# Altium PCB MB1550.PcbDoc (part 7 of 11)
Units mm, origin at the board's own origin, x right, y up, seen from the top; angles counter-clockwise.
Board outline 154.81 x 170.69 mm, 6 copper layers (Top Layer, Signal Layer 1, Signal Layer 2, Signal Layer 3, Signal Layer 4, Bottom Layer), stack 1.49 mm thick; 810 components, 633 nets, 2973 pads, 2150 vias.
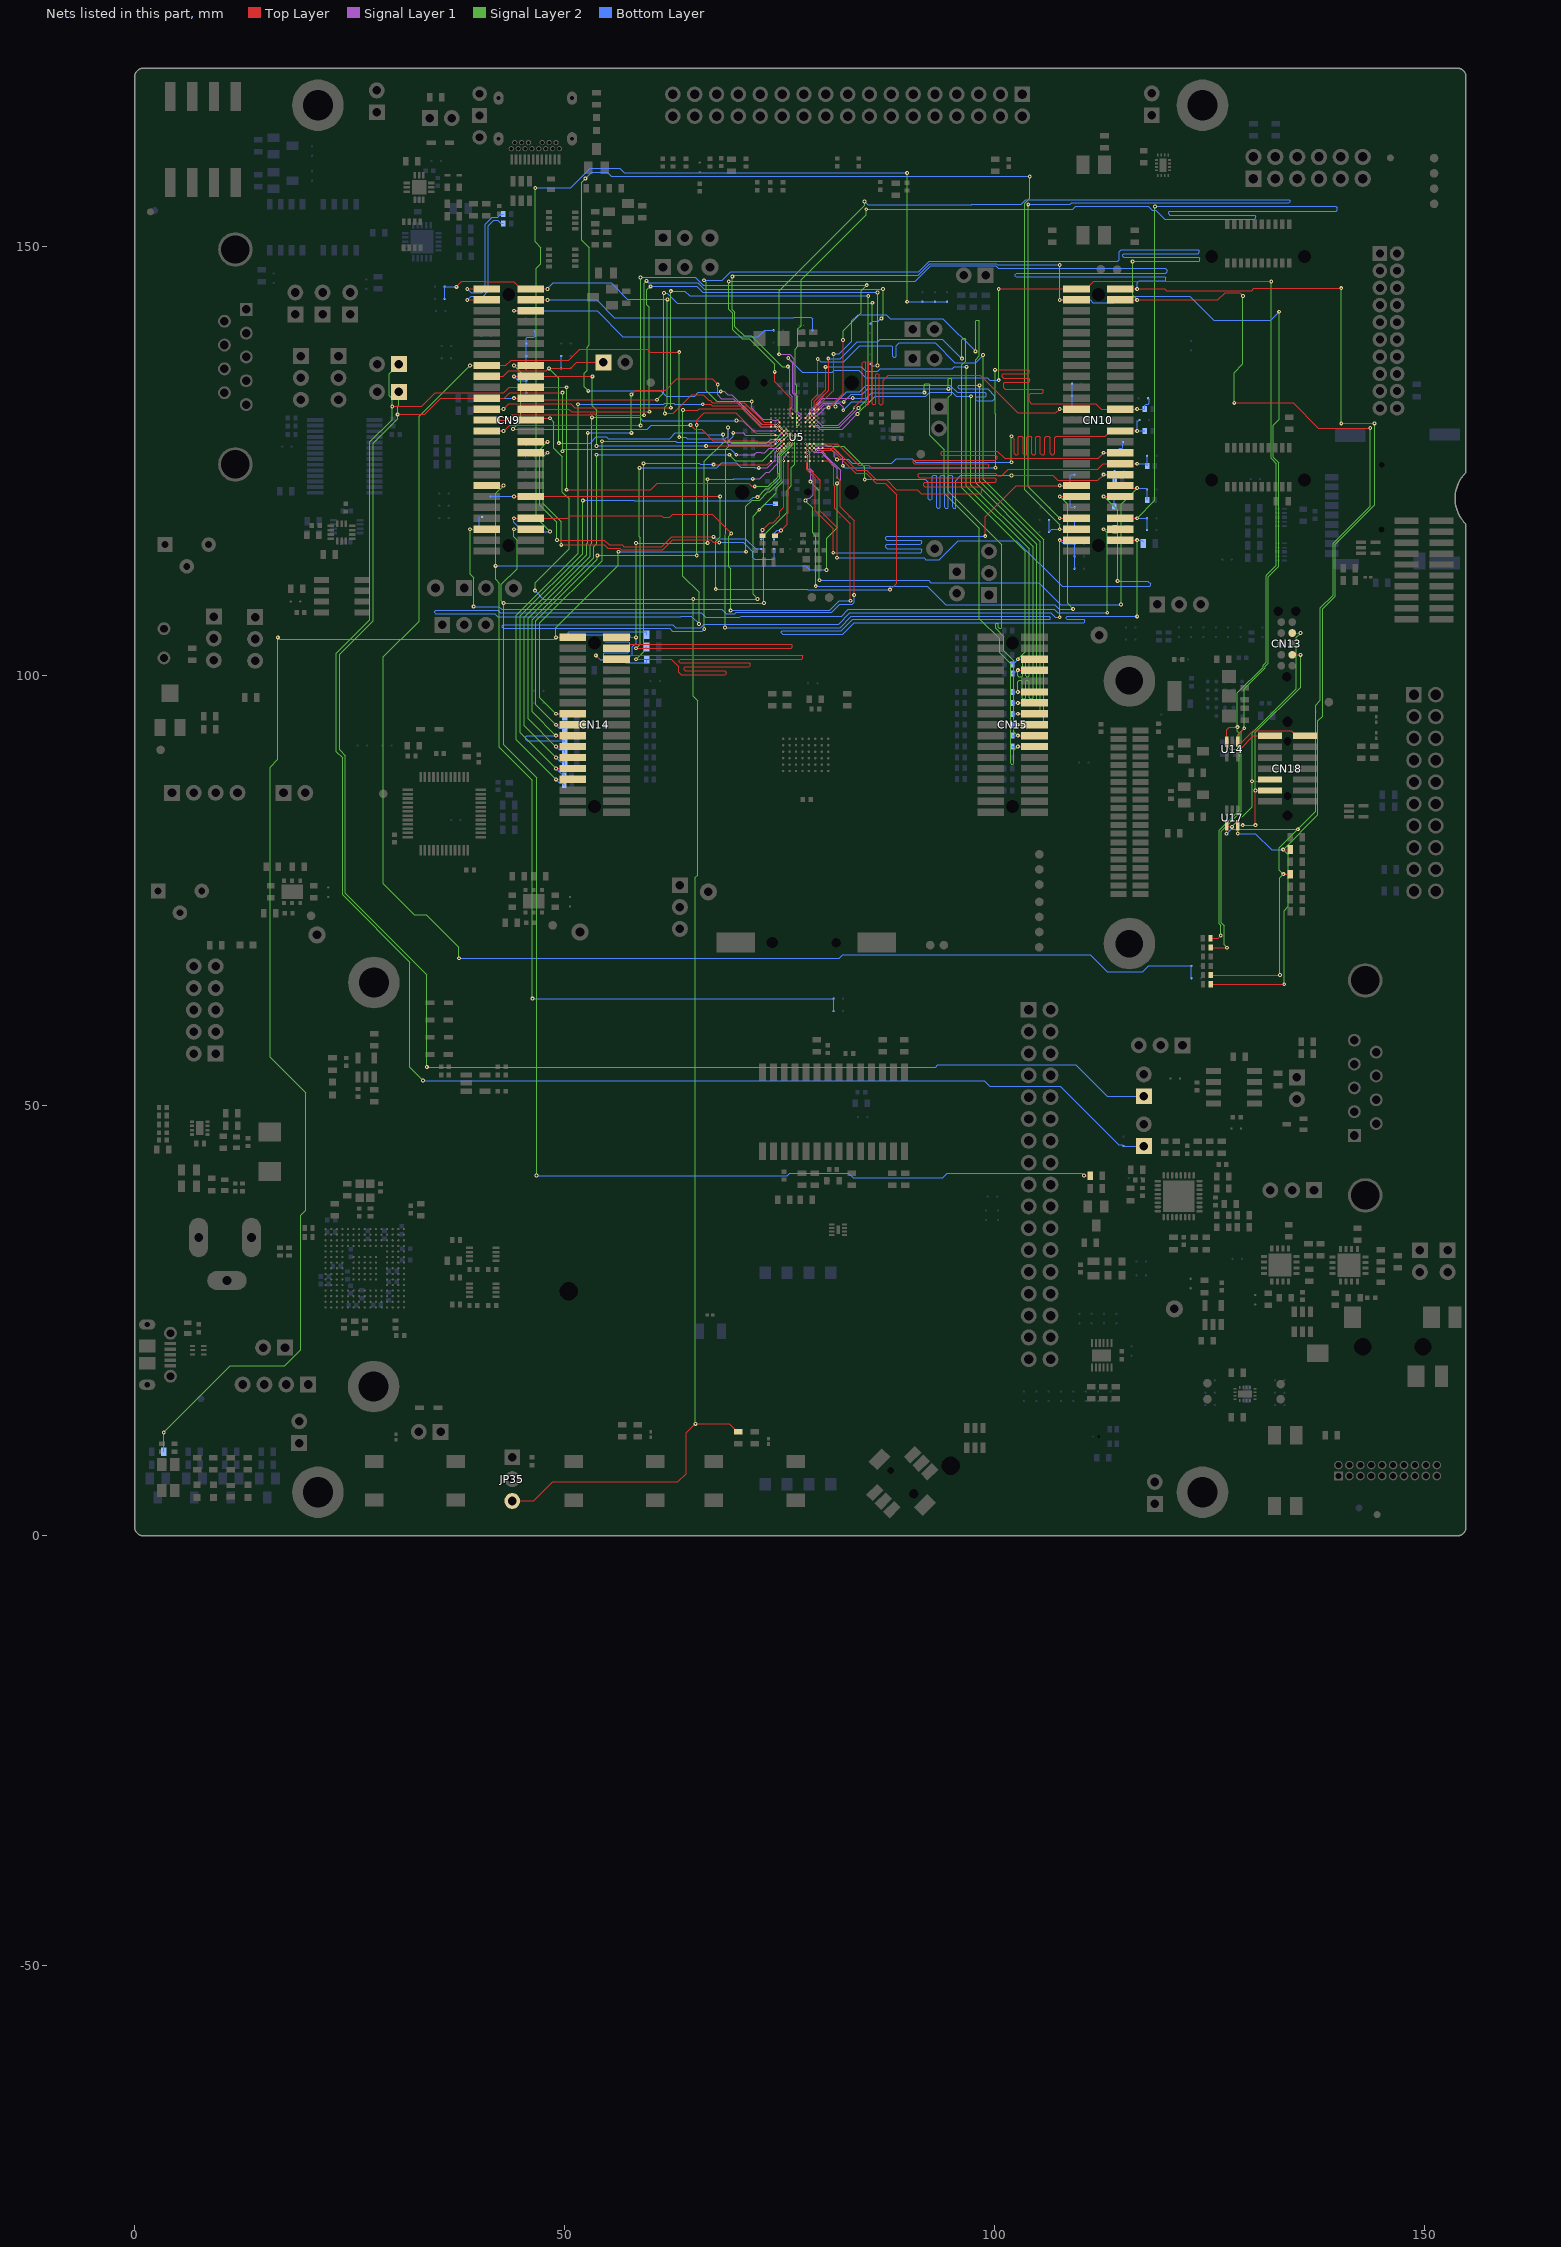
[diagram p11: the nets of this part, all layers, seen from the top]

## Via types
v1: diameter 0.45, hole 0.2, Top Layer to Bottom Layer, tented both sides, 1777 vias
v2: diameter 0.25, hole 0.1, Top Layer to Signal Layer 1, tented top, 344 vias
v3: diameter 0.25, hole 0.1, Signal Layer 1 to Signal Layer 2, 29 vias

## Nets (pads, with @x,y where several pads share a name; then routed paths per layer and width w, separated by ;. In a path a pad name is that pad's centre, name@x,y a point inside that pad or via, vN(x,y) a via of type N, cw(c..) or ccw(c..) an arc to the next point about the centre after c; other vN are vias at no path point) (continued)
PA4: CN9.44 SB16.1 SB17.1 SB18.1 U5.N1 | length 178.3
  Top Layer w0.08: U5.N1@80,125 80.65,125 81.315,124.335 81.315,122.191 81.423,122.083 81.423,119.502 82.125,118.8
  Top Layer w0.12: CN9.44@46.043,118.335 50.335,118.335 50.65,118.65 61.252,118.65 61.457,118.445 62.22,118.445 62.575,118.8 67.15,118.8 v1(69.375,116.575) ; 82.125,118.8 83.225,117.7 v1(83.225,108.75)
  Top Layer w0.127: v1(44.097,118.335) CN9.44@46.043,118.335
  Signal Layer 2 w0.12: v1(46.575,156.75) 46.575,150.475 47.225,149.825 47.225,147.925 46.703,147.403 46.703,118.397 v1(48.3,116.8) ; v1(69.3,107.625) 69.3,112.475 69.07,112.705 69.07,116.27 v1(69.375,116.575) ; v1(89.825,143.525) v1(89.825,158.5)
  Bottom Layer w0.12: v1(44.097,118.335) 44.097,117.853 45.15,116.8 v1(48.3,116.8) ; v1(46.575,156.75) 50.715,156.75 52.99,159.025 56.375,159.025 56.9,158.5 v1(89.825,158.5) ; v1(69.3,107.625) 80.796,107.625 81.921,108.75 v1(83.225,108.75) ; v1(89.825,143.525) SB18.1@91.6,143.525 SB17.1@93.05,143.525 SB16.1@94.475,143.525
PA5: CN9.45 SB75.1 SB82.1 U5.K4 | length 79.7
  Top Layer w0.08: U5.K4@78.5,126.5 v2(78.75,126.25)
  Top Layer w0.1: v2(81.675,123.075) 82.035,122.715 82.035,119.69 82.925,118.8
  Top Layer w0.12: 82.925,118.8 83.658,118.067 v1(83.658,109.425)
  Top Layer w0.127: v1(38.997,117.065) CN9.45@40.943,117.065
  Signal Layer 1 w0.08: v2(78.75,126.25) 79,126 79.146,126 79.354,126 79.5,126 ; 79.5,126 79.854,126 80.127,125.727 80.127,125.648 81.675,124.1 v2(81.675,123.075)
  Signal Layer 2 w0.12: v1(38.997,117.065) 38.997,111.853 39.41,111.44 v1(39.41,108.07)
  Bottom Layer w0.12: v1(38.997,117.065) 40.395,117.065 SB82.1@40.405,117.075 ; v1(39.41,108.07) 42.357,108.07 42.677,107.75 68.275,107.75 68.805,107.22 69.795,107.22 69.96,107.385 81.035,107.385 81.995,108.345 83.419,108.345 83.658,108.584 v1(83.658,109.425) ; 40.055,117.075 40.055,118.5
PA6: CN10.34 R158.1 SB57.1 U5.N4 | length 75.2
  Top Layer w0.08: U5.N4@80,126.5 81.375,126.5 83.975,123.9 85.15,123.9 86.237,122.813 86.825,122.813
  Top Layer w0.1: 86.825,122.813 87.446,122.813 88.585,121.675 91,121.675 91.459,121.216 98.35,121.216 98.525,121.391 98.525,121.858 98.35,122.033 91.867,122.033 91.75,122.15 91.75,122.409 91.875,122.534 100.058,122.534 100.175,122.65 100.175,122.9 100.025,123.05 91.25,123.05 91.108,123.192 91.108,123.433 91.25,123.575 100.094,123.575 100.366,123.304 100.85,123.304 101.606,124.06 111.985,124.06 112.61,124.685 CN10.34@114.623,124.685 v1(116.569,124.685)
  Bottom Layer w0.1: v1(116.569,124.685) R158.1@117.71,124.685 ; R158.1@117.725,124.425 R158.1@117.725,124.67 ; SB57.1@117.725,125.6 R158.1@117.725,124.7 ; R158.1@117.71,124.685 R158.1@117.725,124.7 ; R158.1@117.71,124.685 R158.1@117.725,124.67 ; R158.1@117.725,124.67 R158.1@117.725,124.7
PA7: CN10.36 R159.1 SB61.1 U5.J5 | length 69.9
  Top Layer w0.1: v3(78,127) v2(78.25,126.75) ; v1(101.95,123.325) 106.75,123.325 107.322,122.753 112.015,122.753 v1(112.677,123.415) CN10.36@114.623,123.415
  Signal Layer 1 w0.08: v3(78,127) v2(78.25,126.75)
  Signal Layer 2 w0.09: v3(78,127) 80.25,127 80.525,126.725 82.45,126.725 84.9,124.275 v1(84.9,122.85)
  Bottom Layer w0.1: v1(84.9,122.85) 91.95,122.85 92.258,122.542 92.258,120.617 92.408,120.467 92.592,120.467 92.725,120.6 92.725,123.2 92.862,123.336 93.139,123.336 93.25,123.225 93.25,119.625 93.383,119.492 93.55,119.492 93.7,119.642 93.7,123.225 93.811,123.336 94.089,123.336 94.175,123.25 94.175,119.6 94.275,119.5 94.525,119.5 94.6,119.575 94.6,123.225 94.711,123.336 94.989,123.336 95.1,123.225 95.1,119.6 95.208,119.492 95.423,119.492 95.457,119.525 95.457,122.732 96.05,123.325 v1(101.95,123.325) ; v1(112.677,123.415) 113.54,123.415 SB61.1@113.95,123.825 R159.1@113.95,122.625
PA8: CN9.46 R91.1 U5.G7 | length 196.8
  Top Layer w0.08: v3(77,128) v2(77.25,128.25)
  Top Layer w0.12: v1(110.4,41.9) R91.1@111.1,41.9
  Top Layer w0.127: v1(44.097,117.065) CN9.46@46.043,117.065
  Signal Layer 1 w0.08: v3(77,128) v2(77.25,128.25)
  Signal Layer 2 w0.08: 75.875,121.45 75.875,121.625 76.375,122.125 76.375,124.225 76.75,124.6 76.75,127.75 v3(77,128)
  Signal Layer 2 w0.1: 75.628,118.8 75.875,119.047 75.875,121.45
  Signal Layer 2 w0.12: v1(44.097,117.065) 44.097,116.163 44.46,115.8 44.46,112.45 42.65,110.64 42.65,108.725 v1(42.9,108.475) 42.9,92 46.725,88.175 v1(46.725,41.9) ; v1(73.175,108.475) 73.175,116.347 75.628,118.8
  Bottom Layer w0.12: v1(42.9,108.475) v1(73.175,108.475) ; v1(46.725,41.9) 75.875,41.9 76.175,42.2 83,42.2 83.55,41.65 93.975,41.65 94.475,42.15 110.15,42.15 v1(110.4,41.9)
PA9: CN10.1 CN18.14 R66.1 U5.G11 U14.3 | length 165.7
  Top Layer w0.08: U5.G11@77,130 v2(77.25,130.25)
  Top Layer w0.12: v1(100.475,145.005) CN10.1@109.523,145.005 110.655,145.005 111.525,145.875 v1(132.165,145.875) ; R66.1@125.1,69.5 125.975,69.5 v1(126.3,69.825) ; U14.3@126.975,92.35 126.975,93.75 127.275,94.05 v1(128.225,94.05) ; U14.3@127,92.325 127,91.925 127.245,91.68 127.245,91.675 127.42,91.5 128.55,91.5 130.085,93.035 CN18.14@132.018,93.035
  Signal Layer 1 w0.08: v1(76,136.975) 76.025,136.975 76.55,136.45 76.55,132.85 76.84,132.56 76.84,131.082 76.8,131.042 76.8,130.7 v2(77.25,130.25)
  Signal Layer 2 w0.12: v1(100.475,134.4) v1(100.475,145.005) ; v1(126.3,69.825) 126.3,71.025 126.115,71.21 126.115,82.05 128.435,84.37 128.435,93.39 128.225,93.6 v1(128.225,94.05) 128.225,98.025 131.23,101.03 131.23,101.242 131.587,101.6 131.587,111.662 131.728,111.803 132.775,112.85 132.775,124.7 132.165,125.31 v1(132.165,145.875)
  Bottom Layer w0.12: v1(76,136.975) 77.65,135.325 81.125,135.325 81.325,135.525 84.175,135.525 85.027,134.673 99.141,134.673 99.414,134.4 v1(100.475,134.4)
PA10: CN10.3 CN18.13 R68.2 U5.F11 U14.1 | length 182.6
  Top Layer w0.08: v2(76.25,130.25) U5.F11@76.5,130
  Top Layer w0.12: R68.2@125.125,68.4 v1(127.025,68.4) ; U14.1@128.25,92.35 U14.1@128.275,92.35 ; v1(129.025,93.925) 128.275,93.175 U14.1@128.275,92.35 ; CN18.13@136.082,93.035 135.057,93.035 134.467,93.625 130.05,93.625 128.775,92.35 U14.1@128.275,92.35
  Top Layer w0.127: v1(107.577,143.735) CN10.3@109.523,143.735
  Signal Layer 1 w0.08: v1(75.95,135.975) 75.95,135.925 76.2,135.675 76.2,132.733 76.45,132.483 76.45,131.3 76.25,131.1 v2(76.25,130.25)
  Signal Layer 2 w0.1: 74.4,136.85 75.275,135.975 v1(75.95,135.975)
  Signal Layer 2 w0.12: v1(69.5,146.465) 69.5,142.615 69.8,142.315 69.8,140.625 70.87,139.555 71.695,139.555 74.4,136.85 ; v1(107.575,147.8) 107.575,143.737 v1(107.577,143.735) ; v1(127.025,68.4) 126.705,68.72 126.705,70.959 126.355,71.309 126.355,81.95 128.675,84.27 128.675,93.575 v1(129.025,93.925) 129.025,98.486 131.47,100.931 131.47,101.143 131.827,101.5 131.827,111.563 133.015,112.751 133.015,124.799 132.405,125.41 132.405,129.18 133.083,129.858 v1(133.083,142.35)
  Bottom Layer w0.12: v1(69.5,146.465) 69.635,146.6 91.129,146.6 92.474,147.945 100.2,147.945 100.345,147.8 v1(107.575,147.8) ; v1(107.577,143.735) 111.09,143.735 111.413,143.412 113.787,143.412 114.543,144.168 122.707,144.168 125.5,141.375 132.108,141.375 v1(133.083,142.35)
PA11: CN9.1 R139.2 | length 14.9
  Top Layer w0.127: v1(38.673,145.005) CN9.1@40.943,145.005
  Bottom Layer w0.12: v1(38.673,145.005) 39.118,144.56 40.36,144.56 40.745,144.945 40.745,152.532 41.565,153.353 42.213,153.353 42.56,153.7 R139.2@42.875,153.7
PA12: CN9.3 R140.2 | length 14.9
  Top Layer w0.127: v1(38.673,143.735) CN9.3@40.943,143.735
  Bottom Layer w0.12: v1(38.673,143.735) 39.118,144.18 40.517,144.18 41.125,144.788 41.125,152.375 41.722,152.973 42.213,152.973 42.56,152.625 R140.2@42.875,152.625
PA13: CN10.2 CN13.2 CN18.4 R54.2 R72.1 U5.F12 U17.5 | length 269.7
  Top Layer w0.08: v1(74.425,135.362) 74.425,134.2 76.25,132.375 76.25,130.75 U5.F12@76.5,130.5
  Top Layer w0.12: R72.1@125.125,64.15 v1(133.675,64.15) ; v1(128.275,81.675) U17.5@128.275,82.65 v1(128.85,82.65) ; v1(130.335,82.65) v1(130.335,86.685) 131.998,86.685 132.008,86.675 CN18.4@132.018,86.685 ; v1(133.55,79.8) 134.325,79.8 R54.2@134.35,79.825 ; CN13.2@134.61,102.455 v1(135.57,102.455) ; v1(140.311,129.375) v1(144.175,129.375)
  Top Layer w0.127: CN10.2@114.623,145.005 v1(116.569,145.005) 119.767,145.005 119.951,144.821 129.871,144.821 130.15,145.1 v1(140.311,145.1)
  Signal Layer 2 w0.1: 73.85,136.85 74.425,136.275 v1(74.425,135.362)
  Signal Layer 2 w0.12: v1(69.075,145.875) 69.075,142.661 69.56,142.176 69.56,140.287 70.639,139.208 71.492,139.208 73.85,136.85 ; v1(130.335,86.685) 130.335,93.435 135.57,98.67 v1(135.57,102.455) ; v1(133.675,64.15) 133.675,72.725 134.15,73.2 134.15,79.2 v1(133.55,79.8) 137.591,83.841 137.591,94.791 138.131,95.331 138.131,107.806 139.6,109.275 139.6,115.325 144.175,119.9 v1(144.175,129.375) ; v1(140.311,129.375) v1(140.311,145.1)
  Bottom Layer w0.12: v1(69.075,145.875) 90.743,145.875 92.573,147.705 100.1,147.705 100.41,147.395 107.743,147.395 107.748,147.4 119.85,147.4 120.05,147.2 120.05,147 119.9,146.85 102.55,146.85 102.4,146.7 102.4,146.5 102.5,146.4 119.775,146.4 119.875,146.3 119.875,146.025 119.825,145.975 116.844,145.975 116.569,145.7 v1(116.569,145.005) ; v1(128.275,81.675) 130.325,81.675 132.2,79.8 v1(133.55,79.8) ; v1(128.85,82.65) v1(130.335,82.65)
PA14: CN10.4 CN13.4 CN18.6 R58.2 R71.1 U5.C10 U17.4 | length 275.5
  Top Layer w0.08: v2(74.75,129.75) U5.C10@75,129.5
  Top Layer w0.12: R71.1@125.125,65.225 v1(133.175,65.225) ; v1(126.975,81.65) U17.4@126.975,82.65 127.175,82.45 v1(127.6,82.45) ; v1@129.92,87.755 v1(129.93,87.755) 131.818,87.755 CN18.6@132.018,87.955 ; v1(133.575,76.95) R58.2@134.35,76.95 ; CN13.4@134.61,104.995 v1(135.57,104.995)
  Top Layer w0.127: CN10.4@114.623,143.735 v1(116.569,143.735) 125.955,143.735 126.795,144.574 128.501,144.574 v1(128.875,144.2) ; v1(127.862,131.762) 134.713,131.762 137.65,128.825 v1(143.675,128.825)
  Signal Layer 1 w0.08: v1(71.75,131.925) 71.75,131.15 73.025,129.875 74.05,129.875 74.175,129.75 v2(74.75,129.75)
  Signal Layer 2 w0.1: 66.725,132.875 67.675,131.925 v1(71.75,131.925)
  Signal Layer 2 w0.12: v1(66.2,146.025) 66.441,145.784 66.441,133.159 66.725,132.875 ; v1(116.045,148.205) 116.045,144.259 v1(116.569,143.735) ; v1(127.6,82.45) 129.93,84.78 v1(129.93,87.755) 129.93,93.369 135.05,98.489 135.05,104.475 v1(135.57,104.995) ; v1(133.175,65.225) 133.175,76.55 v1(133.575,76.95) 133.12,77.405 133.12,80.035 v1(135.259,82.175) 137.325,84.241 137.325,95.807 137.321,95.811 137.321,96.596 137.891,97.166 137.891,107.905 139.36,109.374 139.36,115.424 143.675,119.739 v1(143.675,128.825)
  Signal Layer 2 w0.127: v1(127.862,131.762) 127.862,135.287 128.875,136.3 v1(128.875,144.2)
  Bottom Layer w0.12: v1(66.2,146.025) 68.325,146.025 69.305,147.005 91.194,147.005 92.394,148.205 114.3,148.205 114.475,148.38 114.475,149.325 114.725,149.575 123.7,149.575 123.8,149.475 123.8,149.25 123.675,149.125 115,149.125 114.875,149 114.875,148.825 115.025,148.675 123.725,148.675 123.875,148.525 123.875,148.3 123.78,148.205 v1(116.045,148.205) ; v1(126.975,81.65) 127.5,82.175 127.6,82.175 v1(135.259,82.175)
PA15: CN9.2 SB15.1 SB19.1 U5.A10 | length 57
  Top Layer w0.08: 73.2,129.5 U5.A10@74,129.5
  Top Layer w0.1: v1(37.4,145.25) 38.055,145.905 40.773,145.905 40.816,145.862 44.103,145.862 44.96,145.005 CN9.2@46.043,145.005 v1(47.989,145.005) ; v1(61.65,130.525) 62.614,130.525 64.769,132.68 66.088,132.68 66.725,132.043 66.904,132.043 67.148,131.8 70.9,131.8 73.2,129.5
  Signal Layer 2 w0.09: v1(61.65,130.525) 61.65,131.25 61.949,131.549 v1(61.949,143.8)
  Bottom Layer w0.1: SB19.1@36.025,143.85 SB15.1@36.025,145.275 36.05,145.25 v1(37.4,145.25) ; v1(47.989,145.005) 48.684,145.7 55.4,145.7 57.3,143.8 v1(61.949,143.8)
PB0: CN10.28 R152.1 SB50.1 U5.K5 | length 65.3
  Top Layer w0.1: U5.K5@78.5,127 v2(78.75,126.75) ; v1(101.95,127.875) 102.275,127.55 102.275,125.875 102.425,125.725 102.65,125.725 102.725,125.8 102.725,127.775 102.825,127.875 103.15,127.875 103.3,127.725 103.3,125.825 103.408,125.717 103.667,125.717 103.75,125.8 103.75,127.775 103.85,127.875 104.175,127.875 104.3,127.75 104.3,125.85 104.433,125.717 104.642,125.717 104.775,125.85 104.775,127.75 104.9,127.875 105.175,127.875 105.325,127.725 105.325,125.85 105.458,125.717 105.717,125.717 105.85,125.85 105.85,127.725 106,127.875 106.275,127.875 106.45,127.7 106.45,125.875 106.608,125.717 106.792,125.717 106.975,125.9 106.975,127.675 107.175,127.875 112.878,127.875 113.498,128.495 CN10.28@114.623,128.495 v1(116.569,128.495)
  Signal Layer 1 w0.08: v2(78.75,126.75) 79,126.5 79.146,126.5 79.354,126.5 80.83,126.5 81.375,125.955 81.375,125.505 81.69,125.19 81.705,125.175 v1(81.675,125.175)
  Signal Layer 2 w0.09: v1(101.95,124.85) v1(101.95,127.875)
  Bottom Layer w0.1: v1(81.675,125.175) 82.975,125.175 83.415,124.735 88.035,124.735 88.575,125.275 90.419,125.275 90.844,124.85 v1(101.95,124.85) ; SB50.1@116.85,129.75 116.781,129.681 116.569,129.681 v1(116.569,128.495) 117.47,128.495 R152.1@117.475,128.5
PB1: CN10.32 R155.1 SB54.1 U5.N5 | length 71.5
  Top Layer w0.08: U5.N5@80,127 81.725,127 84.225,124.5 85.375,124.5 85.675,124.2 86.825,124.2
  Top Layer w0.1: 86.825,124.2 99.2,124.2 99.3,124.3 99.3,124.55 99.15,124.7 90.625,124.7 90.55,124.775 90.55,125 90.644,125.094 100.094,125.094 100.3,125.3 100.3,125.495 100.12,125.675 93.875,125.675 93.8,125.75 93.8,126.025 93.925,126.15 100.3,126.15 101.15,125.3 112.022,125.3 v1(112.677,125.955) CN10.32@114.623,125.955
  Bottom Layer w0.1: v1(112.677,125.955) 114.145,125.955 R155.1@114.15,125.95 114.15,126.1 114.534,126.484 114.834,126.484 114.925,126.575 SB54.1@114.925,127.175
PB2: CN10.24 R148.1 SB45.1 U5.L5 | length 72
  Top Layer w0.1: U5.L5@79,127 v2(79.25,126.75) ; v1(100.05,135.6) 103.925,135.6 104.05,135.475 104.05,135.275 103.9,135.125 100.975,135.125 100.9,135.05 100.9,134.775 101.075,134.6 103.975,134.6 104.075,134.5 104.075,134.25 103.975,134.15 101.2,134.15 101.075,134.025 101.075,133.5 101.258,133.316 105.508,133.316 105.65,133.175 105.65,132.975 105.525,132.85 104.175,132.85 104.025,132.7 104.025,131.925 104.275,131.675 111.751,131.675 112.391,131.035 CN10.24@114.623,131.035 v1(116.569,131.035)
  Signal Layer 1 w0.08: v2(79.25,126.75) 80.975,126.75 82.2,125.525 82.35,125.375 v1(82.35,124.45)
  Signal Layer 2 w0.09: v1(100.05,135.6) 100.05,130.476 100.1,130.426 100.101,130.426 100.101,124.218 v1(100.1,124.216)
  Bottom Layer w0.1: v1(82.35,124.45) 82.584,124.216 v1(100.1,124.216) ; v1(116.569,131.035) 117.46,131.035 R148.1@117.475,131.05 117.475,131.461 117.614,131.6 117.85,131.6 118,131.75 118,132.15 SB45.1@117.85,132.3
PB3: CN9.15 SB114.1 SB115.1 U5.D6 | length 216.1
  Top Layer w0.1: v1(38.99,136.115) CN9.15@40.943,136.115 43.165,136.115 43.773,136.723 50.473,136.723 51.741,137.991 59.628,137.991 59.958,137.662 v1(63.325,137.662) ; v2(75.25,127.25) U5.D6@75.5,127.5
  Signal Layer 1 w0.08: v1(69,128.9) 69,127.394 69.344,127.05 73.5,127.05 73.95,127.5 75,127.5 v2(75.25,127.25)
  Signal Layer 2 w0.09: v1(37.7,67.175) 37.7,68.437 33.904,72.234 32.484,72.234 28.9,75.817 28.9,102.208 33.081,106.389 33.081,130.206 v1(38.99,136.115) ; v1(63.325,127.775) v1(63.325,137.662)
  Bottom Layer w0.1: v1(37.7,67.175) 81.95,67.175 82.35,67.575 111.1,67.575 113.1,65.575 117.2,65.575 117.9,66.275 SB114.1@122.875,66.275 SB115.1@122.875,64.85 ; v1(63.325,127.775) 64.07,127.775 64.277,127.569 68.694,127.569 69,127.875 v1(69,128.9)
PB4: CN9.16 SB26.1 SB32.1 SB37.1 SB40.1 U5.B6 | length 48.4
  Top Layer w0.08: 66.775,127.825 67.218,127.382 72.323,127.382 72.455,127.25 74.25,127.25 U5.B6@74.5,127.5
  Top Layer w0.1: 66.725,127.875 66.775,127.825
  Top Layer w0.12: v1(64.65,129.175) 65.15,128.675 65.925,128.675 66.725,127.875
  Top Layer w0.127: v1(44.097,136.115) CN9.16@46.043,136.115
  Signal Layer 2 w0.12: v1(44,128.725) 44.9,129.625 44.9,135.312 v1(44.097,136.115)
  Bottom Layer w0.12: v1(44,128.725) 44.009,128.716 59.616,128.716 60.075,129.175 v1(64.65,129.175)
  Bottom Layer w0.127: v1(44.097,136.115) 45.21,136.115 SB40.1@45.55,135.775 SB37.1@45.55,137.2 SB32.1@45.55,138.65 45.55,139.25 45.675,139.375 46.425,139.375 46.55,139.5 SB26.1@46.55,140.075
PB5: CN9.17 JP13.1 SB36.1 SB39.1 U5.C6 | length 53.8
  Top Layer w0.08: v2(74.75,127.25) U5.C6@75,127.5
  Top Layer w0.12: CN9.17@40.943,134.845 42.865,134.845 43.49,135.47 47.859,135.47 v1(48.166,135.777) 50.727,135.777 51.425,136.475 JP13.1@54.505,136.475
  Signal Layer 1 w0.08: v1(68.425,128.075) 68.425,127.554 69.094,126.885 72.782,126.885 73.735,126.885 74.1,127.25 v2(74.75,127.25)
  Signal Layer 2 w0.12: v1(48.166,135.777) 49.325,134.618 v1(49.325,127.075)
  Bottom Layer w0.1: 66.725,128.075 v1(68.425,128.075)
  Bottom Layer w0.12: v1(48.166,135.777) 49.598,135.777 SB39.1@49.6,135.775 SB36.1@49.6,137.225 ; v1(49.325,127.075) 52.964,127.075 53.684,127.795 54.841,127.795 55.061,127.575 62.2,127.575 62.885,128.26 66.365,128.26 66.55,128.075 66.725,128.075
PB6: CN9.18 SB41.1 SB43.1 U5.B5 | length 41.4
  Top Layer w0.08: 66.725,126.75 66.775,126.8 73.847,126.8 73.897,126.75 74.104,126.75 ; 74.104,126.75 74.25,126.75 U5.B5@74.5,127
  Top Layer w0.102: v1(66.45,126.75) 66.725,126.75
  Top Layer w0.12: CN9.18@46.043,134.845 v1(53.22,134.845)
  Top Layer w0.127: v1(44.097,134.845) CN9.18@46.043,134.845
  Signal Layer 2 w0.12: v1(53.22,134.845) 53.22,131.405 53.7,130.925 v1(53.7,126.75)
  Bottom Layer w0.12: v1(44.097,134.845) 44.592,134.35 SB41.1@45.55,134.35 SB43.1@45.55,132.925 ; v1(53.7,126.75) v1(66.45,126.75)
PB7: CN14.1 R240.1 U5.F5 | length 185.8
  Top Layer w0.08: v2(76.25,126.75) v3(76.5,127)
  Top Layer w0.127: v1(48.979,104.49) CN14.1@50.925,104.49
  Signal Layer 1 w0.08: v2(76.25,126.75) v3(76.5,127)
  Signal Layer 2 w0.08: 73.82,121.4 75.2,122.78 75.2,125.6 76.5,126.9 v3(76.5,127)
  Signal Layer 2 w0.09: 19.325,37.295 19.889,37.859 19.889,42.05
  Signal Layer 2 w0.1: 71.07,119.72 71.79,120.44 72.69,120.44 73.165,120.915 73.165,120.974 73.591,121.4 73.82,121.4
  Signal Layer 2 w0.102: v1(3.375,12.025) 11.122,19.772 17.439,19.772 19.325,21.658 19.325,37.295 ; 16.64,90.315 15.737,89.412 15.737,55.663 19.889,51.511 19.889,42.05 ; 71.07,118.77 71.07,119.72
  Signal Layer 2 w0.12: 16.64,90.315 v1(16.64,104.49) ; v1(48.979,104.49) 48.979,105.629 56.25,112.9 v1(56.25,114.45) ; 71.07,118.77 71.07,114.48 v1(71.1,114.45)
  Bottom Layer w0.12: v1(3.375,12.025) 3.375,9.8 R240.1@3.4,9.775 ; v1(16.64,104.49) 16.855,104.275 48.764,104.275 v1(48.979,104.49) ; v1(56.25,114.45) v1(71.1,114.45)
PB8: CN9.20 JP14.1 JP29.1 SB119.1 U5.E5 | length 241.5
  Top Layer w0.08: v2(75.75,126.75) v3(76,127)
  Top Layer w0.1: 66.725,122.425 71.4,122.425 71.775,122.05 v1(72.1,122.05)
  Top Layer w0.12: v1(29.95,131.35) 33.35,131.35 34.925,132.925 42.903,132.925 43.553,133.575 CN9.20@46.043,133.575 v1(50.225,133.575) ; v1(50.225,121.65) 60,121.65 60.775,122.425 66.725,122.425
  Signal Layer 1 w0.08: v2(75.75,126.75) v3(76,127)
  Signal Layer 2 w0.08: 74.653,123.003 74.85,123.2 74.85,123.545 74.8,123.595 74.8,125.8 v3(76,127)
  Signal Layer 2 w0.1: v1(72.1,122.05) 73.7,122.05 74.653,123.003
  Signal Layer 2 w0.12: JP14.1@30.72,136.26 29.615,135.155 29.615,132.577 29.95,132.242 v1(29.95,131.35) 29.95,129.825 27.35,127.225 27.35,106.525 23.45,102.625 23.45,91.2 24.175,90.475 24.175,74.55 32,66.725 32,54.475 v1(33.525,52.95) ; v1(50.225,121.65) v1(50.225,133.575)
  Bottom Layer w0.12: v1(33.525,52.95) 98.775,52.95 99.425,52.3 107.62,52.3 114.425,45.495 114.83,45.495 SB119.1@115,45.325 115.005,45.33 JP29.1@117.35,45.33
PB9: CN9.21 JP15.1 JP27.1 U5.D5 | length 224.3
  Top Layer w0.08: v2(75.25,126.75) U5.D5@75.5,127
  Top Layer w0.12: v1(30.575,130.425) 33.7,130.425 35.58,132.305 38.673,132.305 ; CN9.21@40.943,132.305 42.985,132.305 43.63,132.95 v1(49.75,132.95)
  Top Layer w0.127: 38.673,132.305 CN9.21@40.943,132.305
  Signal Layer 1 w0.08: v1(69.95,125.725) 72.055,125.725 72.355,126.025 72.78,126.025 72.83,125.975 73.275,125.975 73.8,126.5 74.5,126.5 75,126.5 v2(75.25,126.75)
  Signal Layer 2 w0.12: JP15.1@30.72,133.035 30.72,131.52 30.575,131.375 v1(30.575,130.425) 30.575,129.9 27.75,127.075 27.75,106.425 23.825,102.5 23.825,91.4 24.5,90.725 24.5,74.725 33.97,65.255 v1(33.97,54.525) ; v1(49.75,126.13) v1(49.75,132.95)
  Bottom Layer w0.1: 66.725,126.35 69.325,126.35 v1(69.95,125.725)
  Bottom Layer w0.12: v1(33.97,54.525) 93.125,54.525 93.4,54.8 109.45,54.8 113.12,51.13 JP27.1@117.35,51.13 ; v1(49.75,126.13) 49.97,126.35 53.527,126.35 53.532,126.345 66.618,126.345 66.623,126.35 66.725,126.35
PB10: CN9.22 SB46.2 U5.K9 | length 77
  Top Layer w0.08: U5.K9@78.5,129 v2(78.75,129.25)
  Top Layer w0.12: CN9.22@46.043,132.305 46.043,132.12 v1(60.73,132.12)
  Top Layer w0.127: v1(44.097,132.305) CN9.22@46.043,132.305
  Signal Layer 1 w0.08: v2(78.75,129.25) 79,129 79.362,129 ; 79.362,128.994 79.636,128.72 82.295,128.72 v1(84.05,130.475)
  Signal Layer 2 w0.102: v1(84.05,130.475) 85.781,132.206 85.781,136.956
  Signal Layer 2 w0.12: v1(60.73,132.12) 61.544,132.934 61.544,144.524 v1(61.55,144.53) ; 85.781,136.956 v1(85.781,143.4)
  Bottom Layer w0.12: SB46.2@41.625,132.3 44.092,132.3 v1(44.097,132.305) ; v1(61.55,144.53) 61.92,144.53 63.08,143.37 85.751,143.37 v1(85.781,143.4)
PB11: CN9.23 SB49.2 U5.L9 | length 79.7
  Top Layer w0.08: U5.L9@79,129 v2(79.25,129.25)
  Top Layer w0.12: v1(42.889,131.035) 43.504,131.65 50.725,131.65 51.18,131.195 v1(62.35,131.195)
  Top Layer w0.127: CN9.23@40.943,131.035 v1(42.889,131.035)
  Signal Layer 1 w0.08: v2(79.25,129.25) 79.335,129.165 79.46,129.165 79.674,128.95 81.95,128.95 v1(84.175,131.175)
  Signal Layer 2 w0.1: v1(84.175,131.175) 85.3,132.3 85.3,136.85
  Signal Layer 2 w0.12: v1(62.35,131.195) 62.354,131.199 62.354,144.746 v1(62.35,144.75) ; 85.3,136.85 v1(85.3,144.2)
  Bottom Layer w0.12: SB49.2@41.633,130.85 41.818,131.035 v1(42.889,131.035) ; v1(62.35,144.75) 63.988,144.75 64.538,144.2 v1(85.3,144.2)
PB12: CN10.23 SB42.1 SB44.1 SB47.1 U5.L10 | length 67.5
  Top Layer w0.08: U5.L10@79,129.5 v2(79.25,129.75)
  Top Layer w0.1: v2(83.625,131.2) 84.613,132.188 84.613,136.413 84.75,136.55 84.925,136.55 85.025,136.45 85.025,131.6 85.1,131.525 85.25,131.525 85.35,131.625 85.35,136.45 85.425,136.525 85.65,136.525 85.75,136.425 85.75,131.65 85.825,131.575 86.075,131.575 86.15,131.65 86.15,135.075 86.25,135.175 86.462,135.175 86.575,135.062 86.575,131.65 86.675,131.55 86.825,131.55
  Top Layer w0.13: 86.825,131.55 86.9,131.55 87.05,131.7 87.05,134.375 87.621,134.946 98.304,134.946 102.66,130.59 107.132,130.59 v1(107.577,131.035) CN10.23@109.523,131.035
  Signal Layer 1 w0.08: v2(79.25,129.75) 79.266,129.75 79.866,129.15 81.38,129.15 81.67,129.15 81.825,129.15 82.296,129.621 83.625,130.95 v2(83.625,131.2)
  Bottom Layer w0.13: v1(107.577,131.035) 108.885,131.035 SB47.1@109,131.15 SB44.1@109,132.575 SB42.1@109,134
PB13: CN9.24 SB34.2 | length 64.9
  Top Layer w0.12: CN9.24@46.043,131.035 50.49,131.035 50.803,130.722 v1(59.845,130.722)
  Signal Layer 2 w0.1: v1(86.38,136.1) 86.38,136.85
  Signal Layer 2 w0.12: v1(59.845,130.722) 59.845,142.882 59.554,143.174 59.554,144.898 v1@59.99,145.333 ; 86.38,136.85 v1(86.38,144.595)
  Bottom Layer w0.1: SB34.2@85.575,136.275 85.75,136.1 v1(86.38,136.1)
  Bottom Layer w0.12: v1(59.994,145.311) 65.345,145.311 66.051,144.605 86.37,144.605 v1(86.38,144.595)
PB14: CN9.25 SB23.2 | length 67.3
  Top Layer w0.12: CN9.25@40.943,129.765 43.215,129.765 43.83,130.38 52.907,130.38 53.007,130.48 53.445,130.48 53.608,130.317 v1(59.242,130.317)
  Signal Layer 2 w0.12: v1(59.242,130.317) 59.242,145.665 v1(59.526,145.949) ; v1(86.825,141.575) 87.025,141.775 v1(87.025,145)
  Bottom Layer w0.12: v1(59.526,145.949) 59.736,145.738 65.487,145.738 66.225,145 v1(87.025,145) ; SB23.2@85.575,140.975 85.825,141.225 86.475,141.225 v1(86.825,141.575)
PB15: CN9.27 SB52.2 U5.L11 | length 81.6
  Top Layer w0.08: U5.L11@79,130 v2(79.25,130.25)
  Top Layer w0.1: v1(80.7,131.2) 82.375,132.875 82.375,136.85
  Top Layer w0.12: v1(42.889,128.495) 42.96,128.495 43.595,129.13 v1(58.837,129.13) ; 82.375,136.85 v1(82.375,139.06)
  Top Layer w0.127: CN9.27@40.943,128.495 v1(42.889,128.495)
  Signal Layer 1 w0.08: v2(79.25,130.25) 79.375,130.25 80.325,131.2 v1(80.7,131.2)
  Signal Layer 2 w0.12: v1(58.825,146.35) 58.837,146.338 v1(58.837,129.13) ; v1(82.375,139.06) 82.375,140.15 84.47,142.245 84.47,144.795 v1(85.125,145.45)
  Bottom Layer w0.12: SB52.2@41.625,128.5 41.63,128.495 v1(42.889,128.495) ; v1(58.825,146.35) 58.829,146.354 65.211,146.354 66.114,145.45 v1(85.125,145.45)
PC0: CN10.37 R160.1 SB63.1 U5.J2 | length 65.7
  Top Layer w0.08: U5.J2@78,125.5 78.25,125.25 78.25,125.104 78.25,124.896 78.165,124.811 78.165,123.96 79.125,123 79.125,119.21 79.535,118.8
  Top Layer w0.1: 79.535,118.8 81.225,117.11 v1(81.225,114.325) ; v1(98.9,116.257) 98.9,118.525 102.52,122.145 v1(107.577,122.145) CN10.37@109.523,122.145
  Bottom Layer w0.1: v1(81.225,114.325) 91.425,114.325 91.55,114.45 91.55,114.65 91.4,114.8 87.5,114.8 87.35,114.95 87.35,115.175 87.475,115.3 91.375,115.3 91.5,115.425 91.5,115.675 91.4,115.775 87.45,115.775 87.325,115.9 87.325,116.144 87.437,116.257 v1(98.9,116.257) ; v1(107.577,122.145) 108.795,122.145 R160.1@108.8,122.15 108.8,123.306 108.894,123.4 SB63.1@109.3,123.4
PC1: CN10.38 R163.1 SB66.1 U5.J3 | length 70.7
  Top Layer w0.1: U5.J3@78,126 v2(78.25,125.75) ; CN10.38@114.623,122.145 114.918,121.85 v1(116.575,121.85)
  Signal Layer 1 w0.08: v2(78.25,125.75) 78.25,124.075 78.625,123.7 v1@78.625,122.6
  Signal Layer 2 w0.09: v1(78.575,122.6) 79.621,121.554 v1(79.621,111.125) ; v1(114.7,108.3) 114.7,119.975 v1(116.575,121.85)
  Bottom Layer w0.1: v1(79.621,111.125) 92.325,111.125 92.599,110.851 105.15,110.851 107.702,108.3 v1(114.7,108.3) ; v1(116.575,121.85) 117.575,121.85 SB66.1@117.725,121.7 R163.1@117.725,120.475
PC2: CN10.39 R162.1 SB73.1 U5.J4 | length 67.1
  Top Layer w0.1: U5.J4@78,126.5 v2(78.25,126.25) ; v1(107.577,120.875) CN10.39@109.523,120.875
  Signal Layer 1 w0.08: v1(78,120.4) 78.275,120.675 78.5,120.675 78.925,121.1 78.925,123.725 78.5,124.15 78.5,126 v2(78.25,126.25)
  Signal Layer 2 w0.09: v1(78,120.4) 78.829,119.571 78.829,116.646 79.2,116.275 v1(79.2,110.45) ; v1(107.577,120.875) 108.477,119.975 108.477,108.432 v1(109.125,107.784)
  Bottom Layer w0.1: v1(79.2,110.45) 92.15,110.45 94.289,108.311 106.973,108.311 107.5,107.784 v1(109.125,107.784) ; v1(107.577,120.875) R162.1@108.8,120.875 108.8,119.625 SB73.1@109.3,119.625
PC3: CN10.40 R164.1 SB69.1 U5.K1 | length 71.4
  Top Layer w0.08: U5.K1@78.5,125 78.5,123.975 79.7,122.775 79.7,121.75 ; 79.69,121.74 79.69,119.235 80.125,118.8
  Top Layer w0.1: 79.69,121.74 79.7,121.75 ; 80.125,118.8 81.675,117.25 v1(81.675,113.75) ; v1(112.677,120.875) CN10.40@114.623,120.875
  Signal Layer 2 w0.09: v1(112.677,120.875) 114.304,119.248 v1(114.304,111.038)
  Bottom Layer w0.1: v1(81.675,113.75) 91.8,113.75 92.011,113.539 93.571,113.539 95.781,115.749 102.531,115.749 107.854,110.425 118.025,110.425 118.125,110.525 118.125,110.7 117.787,111.038 v1(114.304,111.038) ; v1(112.677,120.875) SB69.1@113.917,120.875 ; R164.1@113.917,119.716 SB69.1@113.917,120.875 ; SB69.1@113.917,120.966 SB69.1@113.917,120.875
PC4: CN9.37 SB116.1 SB117.1 U5.L4 | length 155.4
  Top Layer w0.08: U5.L4@79,126.5 v2(79.25,126.25)
  Top Layer w0.127: CN9.37@40.943,122.145 v1(42.889,122.145)
  Signal Layer 1 w0.08: v2(79.25,126.25) 79.837,126.25 80.317,125.77 80.317,125.692 82.075,123.933 82.075,122.8 v1(81.675,122.4)
  Signal Layer 2 w0.1: 81.675,118.8 v1(81.675,122.4)
  Signal Layer 2 w0.12: v1(42.889,122.145) 41.969,121.225 v1(41.969,112.806) 41.969,111.236 42.41,110.795 42.41,91.69 46.25,87.85 v1(46.25,62.475) ; v1(80.45,112.325) 80.45,115.99 81.675,117.215 81.675,118.8
  Bottom Layer w0.12: v1(41.969,112.806) 41.98,112.795 78.005,112.795 78.475,112.325 v1(80.45,112.325) ; v1(46.25,62.475) SB116.1@81.275,62.475 SB117.1@81.275,61.025
PC5: CN9.40 SB70.1 U5.M4 | length 80.7
  Top Layer w0.08: U5.M4@79.5,126.5 79.75,126.25 81.175,126.25 83.85,123.575 85.05,123.575 86.225,122.4 86.825,122.4
  Top Layer w0.1: 66.725,120.875 v1(68.075,120.875)
  Top Layer w0.12: CN9.40@46.043,120.875 66.725,120.875 ; 86.825,122.4 87.275,122.4 88.6,121.075 88.6,110.798 v1(87.839,110.036)
  Top Layer w0.127: v1(44.097,120.875) CN9.40@46.043,120.875
  Signal Layer 2 w0.1: 68.075,118.8 v1(68.075,120.875)
  Signal Layer 2 w0.12: v1(67.57,110.1) 67.57,115.693 68.075,116.198 68.075,118.8
  Bottom Layer w0.12: SB70.1@41.4,120.875 v1(44.097,120.875) ; v1(67.57,110.1) 78.216,110.1 78.28,110.036 79.414,110.036 79.432,110.055 81.456,110.055 81.475,110.036 v1(87.839,110.036)
PC6: CN9.4 SB24.2 | length 35.1
  Top Layer w0.127: CN9.4@46.043,143.735 v1(47.989,143.735)
  Bottom Layer w0.12: v1(47.989,143.735) 53.74,143.735 55.792,141.683 76.662,141.683 76.697,141.718 78.632,141.718 78.825,141.525 SB24.2@78.825,140.2
PC7: CN9.6 SB25.2 | length 33.7
  Top Layer w0.127: v1(44.097,142.465) CN9.6@46.043,142.465
  Bottom Layer w0.12: v1(44.097,142.465) 53.76,142.465 56.76,139.465 72.529,139.465 73.264,140.2 SB25.2@74.3,140.2
PC8: CN10.43 SB80.1 SB84.1 U5.G10 | length 155.6
  Top Layer w0.1: U5.G10@77,129.5 v2(77.25,129.75) ; v1(107.577,118.335) CN10.43@109.523,118.335
  Signal Layer 1 w0.08: v1(74.938,137.412) 76.162,137.412 76.715,136.86 76.715,132.918 77.1,132.533 77.1,130.754 77.5,130.353 77.5,130.146 77.5,130 v2(77.25,129.75)
  Signal Layer 2 w0.09: v1(74.938,137.412) 74.938,144.825 84.875,154.762 v1(84.875,155.175) ; v1(103.915,154.842) 103.915,153.34 103.898,153.323 103.898,122.014 v1(107.577,118.335)
  Bottom Layer w0.1: v1(84.875,155.175) 84.875,155.155 85.219,154.812 97.321,154.812 97.351,154.842 103.075,154.842 103.62,155.387 134.25,155.387 134.35,155.287 134.35,155.15 134.225,155.025 108.95,155.025 108.767,154.842 v1(103.915,154.842) ; v1(107.577,118.335) 109.165,118.335 SB80.1@109.3,118.2 SB84.1@109.3,116.75
PC9: CN10.44 SB77.1 SB83.1 U5.G9 | length 169.2
  Top Layer w0.1: v3(77,129) v2(77.25,129.25) ; CN10.44@114.623,118.335 v1(116.569,118.335)
  Signal Layer 1 w0.08: v3(77,129) v2(77.25,129.25)
  Signal Layer 2 w0.09: v3(77,129) 77,133.775 76.788,133.987 76.788,137.988 77.125,138.325 77.125,140.375 77.5,140.75 77.5,146.05 85.075,153.625 v1(85.075,154.275) ; v1(116.569,118.335) 118.646,120.412 v1(118.646,154.608)
  Bottom Layer w0.1: v1(85.075,154.275) 109.075,154.275 109.408,154.608 117.892,154.608 118.325,154.175 118.75,154.175 119.8,153.125 130.225,153.125 130.375,153.275 130.375,153.475 130.25,153.6 120.375,153.6 120.225,153.75 120.225,153.975 120.3,154.05 139.725,154.05 139.85,154.175 139.85,154.45 139.692,154.608 v1(118.646,154.608) ; v1(116.569,118.335) 117.71,118.335 SB77.1@117.725,118.35 SB83.1@117.725,116.975
PC10: CN10.45 SB81.1 SB85.1 U5.C9 | length 150
  Top Layer w0.1: v2(74.75,129.25) U5.C9@75,129 ; v1(107.577,117.065) CN10.45@109.523,117.065
  Signal Layer 1 w0.08: v1(68.15,133.1) 68.575,133.1 68.975,132.7 69.4,132.7 72.85,129.25 v2(74.75,129.25)
  Signal Layer 2 w0.09: v1(52.4,157.85) 51.975,157.425 51.975,150.682 52.861,149.796 52.861,138.495 52.605,138.239 52.605,135.54 52.275,135.21 52.275,133.625 v1(52.742,133.158) ; v1(104.075,158.09) 104.075,155.567 103.501,154.993 103.501,121.674 107.577,117.598 v1(107.577,117.065)
  Bottom Layer w0.1: v1(52.4,157.85) 53.126,158.576 54.942,158.576 55.427,158.09 56.725,158.09 56.729,158.087 89.996,158.087 90,158.09 v1(104.075,158.09) ; v1(52.742,133.158) 61.192,133.158 61.808,132.542 65.127,132.542 65.56,132.975 68.025,132.975 v1(68.15,133.1) ; SB81.1@106.325,118.15 SB85.1@106.325,116.725 106.665,117.065 v1(107.577,117.065)
PC11: CN10.46 R168.1 U5.A9 | length 160.7
  Top Layer w0.1: v1(63.75,130.925) 65.458,130.925 65.633,131.1 70.625,131.1 72.725,129 U5.A9@74,129 ; v1(112.677,117.065) CN10.46@114.623,117.065
  Signal Layer 2 w0.09: v1(63.75,130.925) 63.75,111.612 65.626,109.736 v1(65.626,106.049) ; v1(112.677,117.065) 113.089,116.653 v1(113.089,107.351)
  Bottom Layer w0.1: v1(65.626,106.049) 64.716,106.959 63.556,106.959 63.497,106.9 42.2,106.9 41.85,107.25 34.975,107.25 34.9,107.325 34.9,107.55 35,107.65 42.193,107.65 42.506,107.337 65.854,107.337 66.384,106.806 70.382,106.806 70.547,106.972 82.207,106.972 83.003,107.768 106.927,107.768 107.344,107.351 v1(113.089,107.351) ; v1(112.677,117.065) R168.1@114.015,117.065
  Bottom Layer w0.127: R168.1@114.015,117.065 R168.1@114.025,117.075
PC12: CN10.47 SB91.1 SB92.1 SB94.1 U5.E8 | length 137.1
  Top Layer w0.1: v2(75.75,128.75) v3(76,128.5) ; v1(107.577,115.795) CN10.47@109.523,115.795
  Signal Layer 1 w0.08: v2(75.75,128.75) v3(76,128.5)
  Signal Layer 2 w0.09: v1(66.224,105.451) 66.224,124.949 68.475,127.2 74.225,127.2 75.525,128.5 v3(76,128.5) ; v1(107.575,106.825) 107.575,115.793 v1(107.577,115.795)
  Bottom Layer w0.1: v1(66.224,105.451) 65.99,105.217 62.533,105.217 62.2,105.55 42.85,105.55 42.75,105.65 42.75,105.85 42.875,105.975 62.55,105.975 62.893,105.632 65.799,105.632 66.209,106.042 81.867,106.042 83.176,107.351 106.524,107.351 107.05,106.825 v1(107.575,106.825) ; v1(107.577,115.795) 108.022,115.35 SB91.1@109.3,115.35 SB92.1@109.3,113.9 SB94.1@109.3,112.475
PC13: C146.2 CN9.26 JP35.3 R125.1 U5.E3 | length 201.8
  Top Layer w0.08: v2(75.75,125.75) U5.E3@76,126
  Top Layer w0.12: JP35.3@43.9,4.06 46.41,4.06 48.625,6.275 63.175,6.275 64.15,7.25 64.15,11.975 v1(65.2,13.025) 69.125,13.025 70.05,12.1 R125.1@70.2,12.1 ; CN9.26@46.043,129.765 46.253,129.975 v1(48.3,129.975)
  Signal Layer 1 w0.08: v3(75.45,125.05) 75.45,125.363 75.75,125.663 v2(75.75,125.75)
  Signal Layer 2 w0.08: 74.6,121.425 74.6,121.85 75.45,122.7 v3(75.45,125.05)
  Signal Layer 2 w0.1: v1(72.625,119.325) 74.6,121.3 74.6,121.425
  Signal Layer 2 w0.12: v1(46.55,109.925) 46.55,110.825 50.525,114.8 50.525,120.593 49.725,121.393 49.725,125.5 48.75,126.475 48.75,129.525 v1(48.3,129.975) ; v1(64.95,108.95) 64.95,97.617 65.476,97.091 65.476,76.851 65.2,76.575 v1(65.2,13.025) ; v1(72.425,108.95) 71.9,109.475 71.9,118.6 v1(72.625,119.325)
  Bottom Layer w0.1: v1(72.625,119.325) 73.275,119.975 74.425,119.975 C146.2@74.5,120.05
  Bottom Layer w0.12: v1(46.55,109.925) 47.525,108.95 v1(64.95,108.95) v1(72.425,108.95)
PC14: CN9.30 SB87.1 | length 39.7
  Top Layer w0.12: v1(49.1,115.8) 54.625,115.8 55.175,115.25 56.675,115.25 56.875,115.05 61.3,115.05 62.425,116.175 v1(67.3,116.175)
  Top Layer w0.127: CN9.30@46.043,127.225 v1(47.989,127.225)
  Signal Layer 2 w0.12: v1(47.989,127.225) 47.1,126.336 47.1,119.85 49.1,117.85 v1(49.1,115.8)
  Bottom Layer w0.12: v1(67.3,116.175) 67.5,115.975 71,115.975 72.2,114.775 SB87.1@72.85,114.775
PC14-OSC32_IN: R27.1 SB87.2 U5.D1 | length 11.1
  Top Layer w0.12: R27.1@73,116.325 v1(73,116.975) 73.825,117.8 74.225,117.8 75.03,118.605 75.03,119.18 75.5,119.65 U5.D1@75.5,125
  Bottom Layer w0.12: SB87.2@72.85,115.875 73,116.025 v1(73,116.975)
PC15: CN9.32 SB86.1 | length 41.6
  Top Layer w0.12: v1(49.6,115.25) 54.625,115.25 55.02,114.855 56.418,114.855 56.573,114.7 61.425,114.7 62.585,115.86 66.965,115.86 67.3,115.525 v1(67.975,115.525)
  Top Layer w0.127: CN9.32@46.043,125.955 v1(47.989,125.955)
  Signal Layer 2 w0.12: v1(47.989,125.955) 47.525,125.491 47.525,120.025 49.6,117.95 v1(49.6,115.25)
  Bottom Layer w0.12: v1(67.975,115.525) 70.775,115.525 71.875,114.425 71.875,113.775 72.075,113.575 74.275,113.575 74.35,113.65 SB86.1@74.35,114.775
PC15-OSC32_OUT: R28.1 SB86.2 U5.E1 | length 11
  Top Layer w0.12: R28.1@74.45,116.325 74.55,116.325 75.875,117.65 75.875,118.854 76,118.98 76,123.868 U5.E1@76,125
  Bottom Layer w0.12: SB86.2@74.35,115.875 74.35,116.575 74.7,116.925 v1(75.15,116.925)
PD0: CN14.27 R228.2 U5.B9 | length 75.8
  Top Layer w0.08: 73,129.25 74.25,129.25 U5.B9@74.5,129
  Top Layer w0.1: v1(48.979,87.98) CN14.27@50.925,87.98 ; v1(66.05,131.6) 67,131.6 67.15,131.45 70.8,131.45 73,129.25
  Signal Layer 2 w0.09: v1(48.979,87.98) 44.375,92.584 44.375,107.069 51.55,114.244 v1(51.55,131.6)
  Bottom Layer w0.1: v1(48.979,87.98) 49.434,87.525 49.705,87.525 R228.2@49.934,87.296 ; v1(51.55,131.6) 61.52,131.6 61.628,131.708 62.675,131.708 62.783,131.6 v1(66.05,131.6)
PD1: CN14.25 R224.2 U5.F6 | length 69.1
  Top Layer w0.1: v1(48.979,89.25) CN14.25@50.925,89.25 ; v2(76.25,127.25) v3(76.5,127.5)
  Signal Layer 1 w0.08: v2(76.25,127.25) v3(76.5,127.5)
  Signal Layer 2 w0.08: v1(72.425,120.8) 73.375,121.75 73.75,121.75 75.015,123.015 75.015,123.613 75,123.628 75,125.7 76.05,126.75 76.104,126.75 76.25,126.896 76.25,127.103 v2(76.25,127.25) v3(76.5,127.5)
  Signal Layer 2 w0.09: v1(48.979,89.25) 44.85,93.379 44.85,106.975 52.117,114.242 v1(52.117,120.417)
  Bottom Layer w0.1: v1(48.979,89.25) 49.579,88.65 49.934,88.65 R224.2@49.934,88.396 ; v1(52.117,120.417) 58.036,120.417 58.064,120.389 71.489,120.389 71.9,120.8 v1(72.425,120.8)
PD2: CN10.48 R171.2 U5.F7 | length 159.1
  Top Layer w0.1: v2(76.25,128.25) v3(76.5,128) ; CN10.48@114.623,115.795 v1(116.569,115.795)
  Signal Layer 1 w0.08: v2(76.25,128.25) v3(76.5,128)
  Signal Layer 2 w0.08: 75.775,128.25 v2(76.25,128.25) v3(76.5,128)
  Signal Layer 2 w0.09: v1(68.65,105.625) 68.65,116.417 68.75,116.517 68.75,126.375 69.139,126.764 74.289,126.764 75.775,128.25 ; v1(116.569,106.934) v1(116.569,115.795)
  Bottom Layer w0.1: v1(68.65,105.625) 82.04,105.625 83.349,106.934 106.351,106.934 106.475,106.81 106.475,106.625 106.425,106.575 83.499,106.575 82.174,105.25 75.3,105.25 75.2,105.15 75.2,105 75.35,104.85 82.35,104.85 83.675,106.175 110.35,106.175 110.45,106.275 110.45,106.475 110.35,106.575 108.425,106.575 108.35,106.65 108.35,106.834 108.45,106.934 v1(116.569,106.934) ; v1(116.569,115.795) 117.105,115.795 R171.2@117.3,115.6
PD3: CN14.23 R220.2 U5.D8 | length 77.1
  Top Layer w0.08: v2(75.25,128.75) U5.D8@75.5,128.5
  Top Layer w0.1: 66.725,134.55 67.15,134.55 v1(67.8,133.9)
  Top Layer w0.12: v1(57.75,132.725) 58.25,133.225 61.725,133.225 63.05,134.55 66.725,134.55
  Top Layer w0.127: v1(48.979,90.52) CN14.23@50.925,90.52
  Signal Layer 1 w0.08: v1(67.8,133.9) 67.8,132.675 68.225,132.25 69.617,132.25 72.867,129 74.646,129 74.854,129 75,129 v2(75.25,128.75)
  Signal Layer 2 w0.12: v1(48.979,90.52) 45.3,94.199 45.3,106.844 52.549,114.093 52.549,115.36 52.675,115.486 v1(52.675,128.275) ; v1(57.75,128.275) v1(57.75,132.725)
  Bottom Layer w0.12: v1(48.979,90.52) 49.474,90.025 50.009,90.025 R220.2@50.009,89.646 ; v1(52.675,128.275) v1(57.75,128.275)
PD4: CN14.21 R216.2 U5.C8 | length 68.8
  Top Layer w0.1: v1(48.979,91.79) CN14.21@50.925,91.79 ; v2(74.75,128.75) U5.C8@75,128.5
  Signal Layer 1 w0.08: v1(69.975,129.7) 70.7,129.7 71.9,128.5 73.725,128.5 74.5,128.5 v2(74.75,128.75)
  Signal Layer 2 w0.09: v1(48.979,91.79) 45.75,95.019 45.75,106.7 52.95,113.9 52.95,115.194 53.175,115.419 v1(53.175,130.075)
  Bottom Layer w0.1: v1(48.979,91.79) 49.369,91.4 50.009,91.4 R216.2@50.009,91.071 ; v1(53.175,130.075) 58.725,130.075 59.1,129.7 v1(69.975,129.7)
PD5: CN14.19 R210.2 U5.E7 | length 71.8
  Top Layer w0.08: v2(75.75,128.25) v3(76,128)
  Top Layer w0.1: v1(48.979,93.06) CN14.19@50.925,93.06
  Signal Layer 1 w0.08: v2(75.75,128.25) v3(76,128)
  Signal Layer 2 w0.09: v1(48.979,93.06) 46.2,95.839 46.2,106.556 53.375,113.731 53.375,115.025 53.7,115.35 v1(53.7,125.725) ; v1(69.15,125.725) 69.825,125.05 73.05,125.05 v3(76,128)
  Bottom Layer w0.1: v1(48.979,93.06) 45.61,93.06 45.475,92.925 45.475,92.625 45.629,92.471 R210.2@50.009,92.471 ; v1(53.7,125.725) v1(69.15,125.725)
PD6: CN14.17 R206.2 U5.B7 | length 64.6
  Top Layer w0.08: 66.725,130.625 69.9,130.625 72.275,128.25 74.25,128.25 U5.B7@74.5,128
  Top Layer w0.12: v1(65.35,129.175) 65.35,129.75 66.225,130.625 66.725,130.625
  Top Layer w0.127: v1(48.979,94.33) CN14.17@50.925,94.33
  Signal Layer 2 w0.12: v1(48.979,94.33) 46.65,96.659 46.65,106.425 53.8,113.575 v1(53.8,114.012) ; v1(65.35,114.012) v1(65.35,129.175)
  Bottom Layer w0.12: v1(48.979,94.33) 49.388,93.921 R206.2@50.009,93.921 ; v1(53.8,114.012) v1(65.35,114.012)
PD7: CN14.15 R202.2 U5.D7 | length 60.8
  Top Layer w0.08: v2(75.25,128.25) U5.D7@75.5,128
  Top Layer w0.127: v1(48.979,95.6) CN14.15@50.925,95.6
  Signal Layer 1 w0.08: v1(69.6,128.275) 70.75,128.275 71.025,128 75,128 v2(75.25,128.25)
  Signal Layer 2 w0.12: v1(48.979,95.6) 47.1,97.479 47.1,106.175 54.35,113.425 v1(54.35,127.3)
  Bottom Layer w0.1: 66.725,127.155 68.905,127.155 69.6,127.85 v1(69.6,128.275)
  Bottom Layer w0.12: v1(48.979,95.6) 49.755,95.6 R202.2@50.009,95.346 ; v1(54.35,127.3) 62.913,127.3 63.058,127.155 66.725,127.155
PD8: CN15.6 R186.2 U5.L12 | length 71.1
  Top Layer w0.08: U5.L12@79,130.5 79.25,130.75 79.25,130.896 79.25,131.104 79.25,131.75
  Top Layer w0.1: 79.25,131.75 80.724,133.224 80.724,136.827 v1(80.65,136.9) ; v1(102.695,101.95) CN15.6@104.641,101.95
  Signal Layer 2 w0.09: v1(96.2,136.9) 96.2,139.125 96.325,139.25 96.5,139.25 96.625,139.125 96.625,136.6 96.2,136.175 96.2,121.9 103.575,114.525 103.575,102.83 v1(102.695,101.95)
  Bottom Layer w0.1: v1(80.65,136.9) 82.025,136.9 84,138.875 86.385,138.875 86.685,139.175 93.925,139.175 v1(96.2,136.9) ; R186.2@102.025,101.35 102.025,101.625 102.37,101.625 v1(102.695,101.95)
PD9: CN15.8 R190.2 U5.L13 | length 70.3
  Top Layer w0.1: U5.L13@79,131 79,131.925 80.35,133.275 v1(80.35,135.95) ; v1(102.695,100.68) CN15.8@104.641,100.68
  Signal Layer 2 w0.09: v1(96.725,135.95) 96.725,122.05 104,114.775 104,99.999 103.901,99.9 103.7,99.9 103.6,100 103.6,102.025 103.525,102.1 103.399,102.1 103.275,101.976 103.275,100.018 103.175,99.918 102.807,99.918 102.695,100.03 v1(102.695,100.68)
  Bottom Layer w0.1: v1(80.35,135.95) 84.475,135.95 85,135.425 86.4,135.425 86.725,135.75 95.075,135.75 95.275,135.95 v1(96.725,135.95) ; R190.2@102.025,100.275 102.225,100.475 102.49,100.475 v1(102.695,100.68)
PD10: CN15.12 R192.2 U5.K11 | length 70.9
  Top Layer w0.1: U5.K11@78.5,130 v2(78.75,130.25) ; v1(102.695,98.14) CN15.12@104.641,98.14
  Signal Layer 1 w0.08: v2(78.75,130.25) 78.75,130.425 80.04,131.715 81.935,131.715 82.4,131.25 v1(82.4,130.9)
  Signal Layer 2 w0.09: v1(97.25,132.525) 97.25,122.225 104.475,115 104.475,97.479 104.346,97.35 104.134,97.35 104.025,97.459 104.025,99.325 103.875,99.475 103.7,99.475 103.615,99.39 103.615,97.44 103.525,97.35 103.275,97.35 103.2,97.425 103.2,99.375 103.075,99.5 102.85,99.5 102.695,99.345 v1(102.695,98.14)
  Bottom Layer w0.1: v1(82.4,130.9) 83.4,131.9 85.475,131.9 86.1,132.525 92.013,132.525 92.463,132.974 95.061,132.974 95.51,132.525 v1(97.25,132.525) ; R192.2@102.04,98.14 v1(102.695,98.14)
  Bottom Layer w0.127: R192.2@102.025,98.125 R192.2@102.04,98.14
PD11: CN15.14 R196.2 U5.M13 | length 84.9
  Top Layer w0.1: U5.M13@79.5,131 79.5,131.4 81.125,133.025 81.275,133.175 v1(81.275,137.45) ; v1(102.695,96.87) CN15.14@104.641,96.87
  Signal Layer 2 w0.09: v1(97.775,137.75) 97.775,141.25 97.875,141.35 98.125,141.35 98.225,141.25 98.225,137.25 97.775,136.8 97.775,122.45 104.9,115.325 104.9,97.35 104.42,96.87 v1(102.695,96.87)
  Bottom Layer w0.1: v1(81.275,137.45) 81.94,137.45 83.405,138.916 83.405,141.306 84.125,142.025 84.526,142.025 84.531,142.02 85.219,142.02 85.224,142.025 87.375,142.025 87.855,141.545 93.98,141.545 v1(97.775,137.75) ; R196.2@102.03,96.87 v1(102.695,96.87)
  Bottom Layer w0.127: R196.2@102.025,96.875 R196.2@102.03,96.87 ; v1@102.69,96.875 v1(102.695,96.87)
PD12: CN15.16 R199.2 U5.K10 | length 81.3
  Top Layer w0.1: U5.K10@78.5,129.5 v2(78.75,129.75) ; v1(102.695,95.6) CN15.16@104.641,95.6
  Signal Layer 1 w0.08: v2(78.75,129.75) 79,130 79,130.354 80.196,131.55 81.3,131.55 v1(81.5,131.35)
  Signal Layer 2 w0.09: v1(98.25,133.8) 98.25,122.65 105.3,115.6 105.3,96.025 104.875,95.6 v1(102.695,95.6)
  Bottom Layer w0.1: v1(81.5,131.35) 81.5,131.75 82.825,133.075 84.325,133.075 84.814,133.565 84.814,133.568 85.065,133.818 94.807,133.818 95.65,132.975 98.875,132.975 99.025,132.825 99.025,132.575 98.925,132.475 97.925,132.475 97.8,132.35 97.8,132.15 97.95,132 99.775,132 100.025,132.25 100.025,132.55 99.175,133.4 95.875,133.4 95.75,133.525 95.75,133.7 95.85,133.8 v1(98.25,133.8) ; R199.2@102.025,95.6 v1(102.695,95.6)
PD13: CN15.18 R204.2 U5.K12 | length 82.2
  Top Layer w0.08: U5.K12@78.5,130.5 78.75,130.75 78.75,132.075
  Top Layer w0.1: 78.75,132.075 79.425,132.75 v1(79.425,136.85) ; v1(102.695,94.33) CN15.18@104.641,94.33
  Signal Layer 2 w0.09: v1(98.65,137.325) 98.65,122.875 105.7,115.825 105.7,94.575 105.455,94.33 v1(102.695,94.33)
  Bottom Layer w0.1: v1(79.425,136.85) 79.749,136.526 82.426,136.526 84.325,138.425 88.05,138.425 88.15,138.325 88.15,137.186 88.261,137.075 88.425,137.075 88.55,137.2 88.55,138.375 88.9,138.725 93.075,138.725 95.35,136.45 97.775,136.45 v1(98.65,137.325) ; R204.2@102.025,94.33 v1(102.695,94.33)
PD14: CN15.20 R207.2 U5.J10 | length 69.7
  Top Layer w0.1: U5.J10@78,129.5 v2(78.25,129.75) ; v1(102.695,93.06) CN15.20@104.641,93.06
  Signal Layer 1 w0.08: v2(78.25,129.75) 78.5,130 78.5,130.408 78.683,130.592 ; 78.675,130.6 78.675,130.75 79.805,131.88 v1(82.455,131.88)
  Signal Layer 2 w0.09: v1(94.621,133.391) 94.621,134.525 94.721,134.625 94.875,134.625 95,134.5 95,132.78 94.621,132.401 94.621,121.454 100.825,115.25 100.825,105.65 100.75,105.575 100.525,105.575 100.425,105.675 100.425,106.05 100.35,106.125 100.175,106.125 100.1,106.05 100.1,105.525 101.075,104.55 101.075,102.925 102.25,101.75 102.25,93.505 v1(102.695,93.06)
  Bottom Layer w0.1: v1(82.455,131.88) 83.325,132.75 84.6,132.75 85.241,133.391 v1(94.621,133.391) ; R207.2@102.04,93.06 v1(102.695,93.06)
  Bottom Layer w0.127: R207.2@102.025,93.075 R207.2@102.04,93.06
PD15: CN15.22 R213.2 U5.J11 | length 70.1
  Top Layer w0.1: U5.J11@78,130 v2(78.25,130.25) ; v1(102.695,91.79) CN15.22@104.641,91.79
  Signal Layer 1 w0.08: v2(78.25,130.25) 78.25,130.396 78.5,130.646 78.5,130.825 80,132.325 v1(83.5,132.325)
  Signal Layer 2 w0.09: v1(91.825,132.95) 91.825,133.875 91.925,133.975 92.329,133.975 92.429,133.875 92.429,127.996 94.125,126.3 94.125,121.275 98.2,117.2 98.2,106.675 100.575,104.3 100.575,102.704 101.85,101.429 101.85,89.825 101.95,89.725 102.15,89.725 102.25,89.825 102.25,91.345 v1(102.695,91.79)
  Bottom Layer w0.1: v1(83.5,132.325) 85.075,132.325 85.7,132.95 v1(91.825,132.95) ; R213.2@102.035,91.79 v1(102.695,91.79)
  Bottom Layer w0.127: R213.2@102.025,91.8 R213.2@102.035,91.79
PE0: CN14.2 R176.2 U5.D4 | length 79
  Top Layer w0.08: v2(75.25,126.25) U5.D4@75.5,126.5
  Top Layer w0.127: CN14.2@56.025,104.49 v1(58.295,104.49)
  Signal Layer 1 w0.08: v1(71.875,122.925) 72.705,122.925 73.455,123.675 73.775,123.675 73.785,123.685 73.785,123.718 74.85,124.783 74.85,125.482 75,125.632 75,126 v2(75.25,126.25)
  Signal Layer 2 w0.12: v1(58.295,104.49) v1(58.295,115.455) ; v1(66.625,115.455) v1(66.625,122.875)
  Bottom Layer w0.1: v1@66.725,122.875 69.638,122.875 69.688,122.925 v1(71.875,122.925)
  Bottom Layer w0.12: v1(58.295,104.49) 58.295,103.833 57.871,103.409 57.871,102.496 57.7,102.325 54.65,102.325 54.55,102.425 54.55,102.65 54.625,102.725 57.35,102.725 57.425,102.8 57.425,103.05 57.325,103.15 54.675,103.15 54.55,103.275 54.55,103.449 54.651,103.55 57.5,103.55 57.55,103.6 57.55,103.9 57.475,103.975 54.707,103.975 54.625,104.057 54.625,104.3 54.7,104.375 57.5,104.375 57.6,104.475 57.6,104.7 57.515,104.785 50.5,104.785 50.4,104.885 50.4,105.062 50.475,105.137 59.55,105.137 R176.2@59.55,104.8 ; v1(58.295,115.455) v1(66.625,115.455) ; v1(66.625,122.875) v1@66.725,122.875
PE1: CN14.4 R181.2 U5.C4 | length 79.9
  Top Layer w0.1: CN14.4@56.025,103.22 57.145,103.22 57.625,103.7 76.35,103.7 76.45,103.6 76.45,103.325 76.35,103.225 58.3,103.225 v1(58.295,103.22) ; v2(74.75,126.25) U5.C4@75,126.5
  Signal Layer 1 w0.08: v1(72.575,124.2) 73.554,124.2 74.5,125.146 74.5,125.354 74.5,126 v2(74.75,126.25)
  Signal Layer 2 w0.09: v1(58.295,103.22) 58.783,103.708 58.783,116.098 58.691,116.19 v1(58.691,124.2)
  Bottom Layer w0.1: v1(58.295,103.22) R181.2@59.395,103.22 ; v1(58.691,124.2) 67.664,124.2 68.257,124.794 69.953,124.794 70.497,124.25 72.085,124.25 72.125,124.21 72.565,124.21 v1(72.575,124.2)
  Bottom Layer w0.127: R181.2@59.395,103.22 R181.2@59.55,103.375
PE2: CN14.6 R184.2 U5.A1 | length 117.6
  Top Layer w0.1: v1(53.625,102.4) 54.075,101.95 CN14.6@56.025,101.95 57.175,101.95 57.65,102.425 77.6,102.425 77.7,102.325 77.7,102.075 77.575,101.95 63.5,101.95 63.35,101.8 63.35,101.6 63.425,101.525 71.45,101.525 71.55,101.425 71.55,101.2 71.4,101.05 63.975,101.05 63.875,100.95 63.875,100.725 64,100.6 68.625,100.6 68.775,100.45 68.775,100.275 68.625,100.125 63.55,100.125 63.265,100.41 63.265,101.05 62.365,101.95 v1(58.295,101.95) ; v1(67.325,124.575) 73.575,124.575 U5.A1@74,125
  Signal Layer 2 w0.09: v1(58.295,101.95) 59.175,102.83 v1(59.175,124.725)
  Bottom Layer w0.1: v1(53.625,102.4) 54.15,101.875 56.79,101.875 57.098,101.567 59.55,101.567 R184.2@59.55,101.925 R184.2@59.525,101.95 ; v1(59.175,124.725) 65.65,124.725 65.748,124.627 67.273,124.627 v1(67.325,124.575)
